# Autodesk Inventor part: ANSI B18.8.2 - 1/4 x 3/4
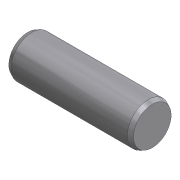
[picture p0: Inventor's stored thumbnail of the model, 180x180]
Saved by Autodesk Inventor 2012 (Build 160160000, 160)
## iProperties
Created: 2000-06
Part Number: ANSI B18.8.2 - 1/4 x 3/4
Material: Stainless Steel, Austenitic
Description: Pin - Unhardened Ground Dowel
Document SubType Name: Standard Catalog Part
Standard: ANSI B18.8.2 - 1/4 x 3/4
Designer: Ron
Density: 1 g/cm^3
Control State: 0
Master: False
Checked Out: False
Shininess: 60.0
Density: 0.0
Volumn: 0.0
Area: 0.0
PropertySet Name: Model Information
Author: Ron
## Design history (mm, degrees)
node "Base1"
body "Solid1"
